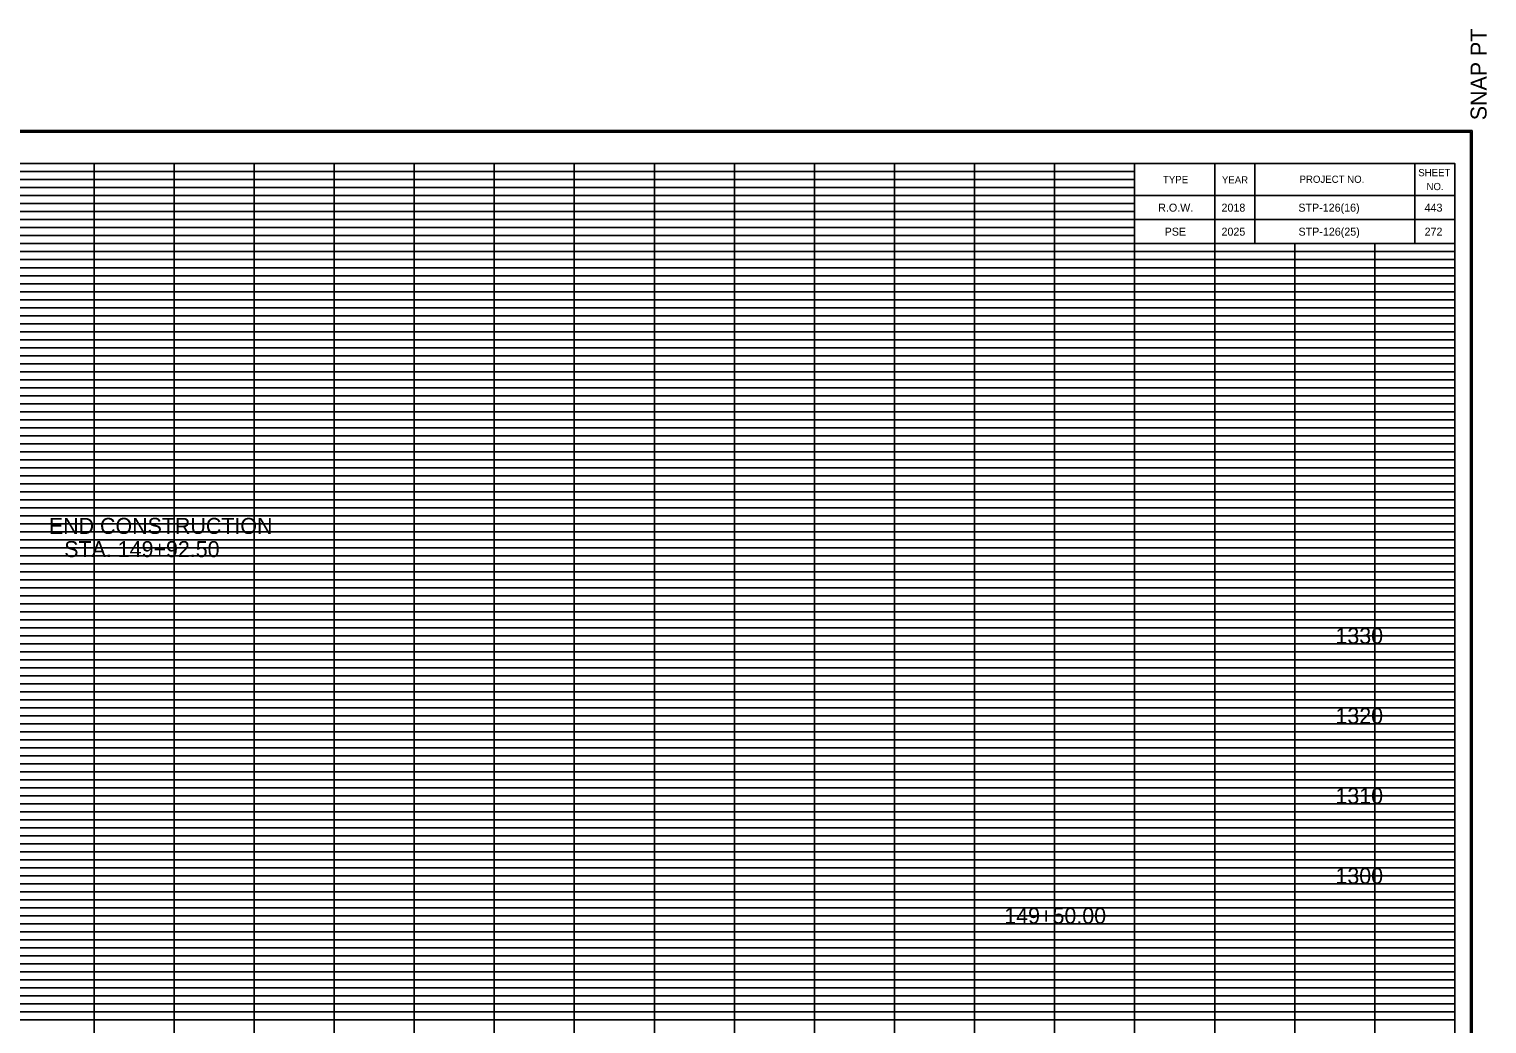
# Model space of a CAD drawing. Extents: x 980 to 1324, y 978 to 1227.
# Drawn here: x 1141.7 to 1323.8, y 1102.3 to 1226.6 of the extents above; entities that cross this region are included whole.
import ezdxf

# ---------------------------------------------------------------- set-up
doc = ezdxf.new("R2010")
doc.units = 0
for name, color, linetype in [('Default', 7, 'Continuous'), ('DESIGN - SCRATCH - User 1', 7, 'Continuous'), ('DESIGN - SHEET - Corner Text', 7, 'Continuous'), ('DESIGN - SHEET - Light Grid', 7, 'Continuous'), ('DESIGN - SHEET - Linework', 7, 'Continuous'), ('DESIGN - SHEET - Plot Shape', 7, 'Continuous'), ('DESIGN - TYPICAL - Text', 7, 'Continuous')]:
    doc.layers.add(name, color=color, linetype=linetype)

# ---------------------------------------------------------------- blocks, each defined once
blk = doc.blocks.new('XSTSHT')
at = {"layer": 'DESIGN - SCRATCH - User 1'}
for p, q in [((28.5, 20.45), (28.5, 20.45)), ((29.24, 20.45), (29.24, 20.45)), ((30.49, 20.45), (30.49, 20.45)), ((31.74, 20.45), (31.74, 20.45)), ((28.5, 20.15), (28.5, 20.15)), ((29.24, 20.15), (29.24, 20.15)), ((30.49, 20.15), (30.49, 20.15)), ((31.74, 20.15), (31.74, 20.15))]:
    blk.add_line(p, q, dxfattribs=at)
at = {"layer": 'DESIGN - SHEET - Light Grid'}
for p, q in [((8, 20.9), (16, 20.9)), ((8, 20.8), (16, 20.8)), ((16, 20.9), (24, 20.9)), ((16, 20.8), (24, 20.8)), ((24, 20.9), (28, 20.9)), ((24, 20.8), (28, 20.8)), ((8, 20.7), (16, 20.7)), ((8, 20.6), (16, 20.6)), ((16, 20.7), (24, 20.7)), ((16, 20.6), (24, 20.6)), ((24, 20.7), (28, 20.7)), ((24, 20.6), (28, 20.6)), ((8, 20.5), (16, 20.5)), ((8, 20.4), (16, 20.4)), ((16, 20.5), (24, 20.5)), ((16, 20.4), (24, 20.4)), ((24, 20.5), (28, 20.5)), ((24, 20.4), (28, 20.4)), ((8, 20.3), (16, 20.3)), ((16, 20.3), (24, 20.3)), ((24, 20.3), (28, 20.3)), ((8, 20.2), (16, 20.2)), ((8, 20.1), (16, 20.1)), ((16, 20.2), (24, 20.2)), ((16, 20.1), (24, 20.1)), ((24, 20.2), (28, 20.2)), ((24, 20.1), (28, 20.1)), ((8, 19.9), (16, 19.9)), ((16, 19.9), (24, 19.9)), ((24, 19.9), (32, 19.9)), ((8, 19.8), (16, 19.8)), ((8, 19.7), (16, 19.7)), ((16, 19.8), (24, 19.8)), ((16, 19.7), (24, 19.7)), ((24, 19.8), (32, 19.8)), ((24, 19.7), (32, 19.7)), ((8, 19.6), (16, 19.6)), ((8, 19.5), (16, 19.5)), ((16, 19.6), (24, 19.6)), ((16, 19.5), (24, 19.5)), ((24, 19.6), (32, 19.6)), ((24, 19.5), (32, 19.5)), ((8, 19.4), (16, 19.4)), ((16, 19.4), (24, 19.4)), ((24, 19.4), (32, 19.4)), ((8, 19.3), (16, 19.3)), ((8, 19.2), (16, 19.2)), ((16, 19.3), (24, 19.3)), ((16, 19.2), (24, 19.2)), ((24, 19.3), (32, 19.3)), ((24, 19.2), (32, 19.2)), ((8, 19.1), (16, 19.1)), ((16, 19.1), (24, 19.1)), ((24, 19.1), (32, 19.1)), ((8, 18.9), (16, 18.9)), ((8, 18.8), (16, 18.8)), ((16, 18.9), (24, 18.9)), ((16, 18.8), (24, 18.8)), ((24, 18.9), (32, 18.9)), ((24, 18.8), (32, 18.8)), ((8, 18.7), (16, 18.7)), ((8, 18.6), (16, 18.6)), ((16, 18.7), (24, 18.7)), ((16, 18.6), (24, 18.6)), ((24, 18.7), (32, 18.7)), ((24, 18.6), (32, 18.6)), ((8, 18.5), (16, 18.5)), ((8, 18.4), (16, 18.4)), ((16, 18.5), (24, 18.5)), ((16, 18.4), (24, 18.4)), ((24, 18.5), (32, 18.5)), ((24, 18.4), (32, 18.4)), ((8, 18.3), (16, 18.3)), ((16, 18.3), (24, 18.3)), ((24, 18.3), (32, 18.3)), ((8, 18.2), (16, 18.2)), ((8, 18.1), (16, 18.1)), ((16, 18.2), (24, 18.2)), ((16, 18.1), (24, 18.1)), ((24, 18.2), (32, 18.2)), ((24, 18.1), (32, 18.1)), ((8, 17.9), (16, 17.9)), ((16, 17.9), (24, 17.9)), ((24, 17.9), (32, 17.9)), ((8, 17.8), (16, 17.8)), ((8, 17.7), (16, 17.7)), ((16, 17.8), (24, 17.8)), ((16, 17.7), (24, 17.7)), ((24, 17.8), (32, 17.8)), ((24, 17.7), (32, 17.7)), ((8, 17.6), (16, 17.6)), ((8, 17.5), (16, 17.5)), ((16, 17.6), (24, 17.6)), ((16, 17.5), (24, 17.5)), ((24, 17.6), (32, 17.6)), ((24, 17.5), (32, 17.5)), ((8, 17.4), (16, 17.4)), ((8, 17.3), (16, 17.3)), ((16, 17.4), (24, 17.4)), ((16, 17.3), (24, 17.3)), ((24, 17.4), (32, 17.4)), ((24, 17.3), (32, 17.3)), ((8, 17.2), (16, 17.2)), ((16, 17.2), (24, 17.2)), ((24, 17.2), (32, 17.2)), ((8, 17.1), (16, 17.1)), ((16, 17.1), (24, 17.1)), ((24, 17.1), (32, 17.1)), ((8, 16.9), (16, 16.9)), ((8, 16.8), (16, 16.8)), ((16, 16.9), (24, 16.9)), ((16, 16.8), (24, 16.8)), ((24, 16.9), (32, 16.9)), ((24, 16.8), (32, 16.8)), ((8, 16.7), (16, 16.7)), ((8, 16.6), (16, 16.6)), ((16, 16.7), (24, 16.7)), ((16, 16.6), (24, 16.6)), ((24, 16.7), (32, 16.7)), ((24, 16.6), (32, 16.6)), ((8, 16.5), (16, 16.5)), ((8, 16.4), (16, 16.4)), ((16, 16.5), (24, 16.5)), ((16, 16.4), (24, 16.4)), ((24, 16.5), (32, 16.5)), ((24, 16.4), (32, 16.4)), ((8, 16.3), (16, 16.3)), ((16, 16.3), (24, 16.3)), ((24, 16.3), (32, 16.3)), ((8, 16.2), (16, 16.2)), ((8, 16.1), (16, 16.1)), ((16, 16.2), (24, 16.2)), ((16, 16.1), (24, 16.1)), ((24, 16.2), (32, 16.2)), ((24, 16.1), (32, 16.1)), ((8, 15.9), (16, 15.9)), ((16, 15.9), (24, 15.9)), ((24, 15.9), (32, 15.9)), ((8, 15.8), (16, 15.8)), ((8, 15.7), (16, 15.7)), ((16, 15.8), (24, 15.8)), ((16, 15.7), (24, 15.7)), ((24, 15.8), (32, 15.8)), ((24, 15.7), (32, 15.7)), ((8, 15.6), (16, 15.6)), ((8, 15.5), (16, 15.5)), ((16, 15.6), (24, 15.6)), ((16, 15.5), (24, 15.5)), ((24, 15.6), (32, 15.6)), ((24, 15.5), (32, 15.5)), ((8, 15.4), (16, 15.4)), ((8, 15.3), (16, 15.3)), ((16, 15.4), (24, 15.4)), ((16, 15.3), (24, 15.3)), ((24, 15.4), (32, 15.4)), ((24, 15.3), (32, 15.3)), ((8, 15.2), (16, 15.2)), ((16, 15.2), (24, 15.2)), ((24, 15.2), (32, 15.2)), ((8, 15.1), (16, 15.1)), ((16, 15.1), (24, 15.1)), ((24, 15.1), (32, 15.1)), ((8, 14.9), (16, 14.9)), ((8, 14.8), (16, 14.8)), ((16, 14.9), (24, 14.9)), ((16, 14.8), (24, 14.8)), ((24, 14.9), (32, 14.9)), ((24, 14.8), (32, 14.8)), ((8, 14.7), (16, 14.7)), ((8, 14.6), (16, 14.6)), ((16, 14.7), (24, 14.7)), ((16, 14.6), (24, 14.6)), ((24, 14.7), (32, 14.7)), ((24, 14.6), (32, 14.6)), ((8, 14.5), (16, 14.5)), ((8, 14.4), (16, 14.4)), ((16, 14.5), (24, 14.5)), ((16, 14.4), (24, 14.4)), ((24, 14.5), (32, 14.5)), ((24, 14.4), (32, 14.4)), ((8, 14.3), (16, 14.3)), ((16, 14.3), (24, 14.3)), ((24, 14.3), (32, 14.3)), ((8, 14.2), (16, 14.2)), ((8, 14.1), (16, 14.1)), ((16, 14.2), (24, 14.2)), ((16, 14.1), (24, 14.1)), ((24, 14.2), (32, 14.2)), ((24, 14.1), (32, 14.1)), ((8, 13.9), (16, 13.9)), ((16, 13.9), (24, 13.9)), ((24, 13.9), (32, 13.9)), ((8, 13.8), (16, 13.8)), ((8, 13.7), (16, 13.7)), ((16, 13.8), (24, 13.8)), ((16, 13.7), (24, 13.7)), ((24, 13.8), (32, 13.8)), ((24, 13.7), (32, 13.7)), ((8, 13.6), (16, 13.6)), ((8, 13.5), (16, 13.5)), ((16, 13.6), (24, 13.6)), ((16, 13.5), (24, 13.5)), ((24, 13.6), (32, 13.6)), ((24, 13.5), (32, 13.5)), ((8, 13.4), (16, 13.4)), ((8, 13.3), (16, 13.3)), ((16, 13.4), (24, 13.4)), ((16, 13.3), (24, 13.3)), ((24, 13.4), (32, 13.4)), ((24, 13.3), (32, 13.3)), ((8, 13.2), (16, 13.2)), ((16, 13.2), (24, 13.2)), ((24, 13.2), (32, 13.2)), ((8, 13.1), (16, 13.1)), ((16, 13.1), (24, 13.1)), ((24, 13.1), (32, 13.1)), ((8, 12.9), (16, 12.9)), ((8, 12.8), (16, 12.8)), ((16, 12.9), (24, 12.9)), ((16, 12.8), (24, 12.8)), ((24, 12.9), (32, 12.9)), ((24, 12.8), (32, 12.8)), ((8, 12.7), (16, 12.7)), ((8, 12.6), (16, 12.6)), ((16, 12.7), (24, 12.7)), ((16, 12.6), (24, 12.6)), ((24, 12.7), (32, 12.7)), ((24, 12.6), (32, 12.6)), ((8, 12.5), (16, 12.5)), ((8, 12.4), (16, 12.4)), ((16, 12.5), (24, 12.5)), ((16, 12.4), (24, 12.4)), ((24, 12.5), (32, 12.5)), ((24, 12.4), (32, 12.4)), ((8, 12.3), (16, 12.3)), ((16, 12.3), (24, 12.3)), ((24, 12.3), (32, 12.3)), ((8, 12.2), (16, 12.2)), ((8, 12.1), (16, 12.1)), ((16, 12.2), (24, 12.2)), ((16, 12.1), (24, 12.1)), ((24, 12.2), (32, 12.2)), ((24, 12.1), (32, 12.1)), ((8, 11.9), (16, 11.9)), ((16, 11.9), (24, 11.9)), ((24, 11.9), (32, 11.9)), ((8, 11.8), (16, 11.8)), ((8, 11.7), (16, 11.7)), ((16, 11.8), (24, 11.8)), ((16, 11.7), (24, 11.7)), ((24, 11.8), (32, 11.8)), ((24, 11.7), (32, 11.7)), ((8, 11.6), (16, 11.6)), ((8, 11.5), (16, 11.5)), ((16, 11.6), (24, 11.6)), ((16, 11.5), (24, 11.5)), ((24, 11.6), (32, 11.6)), ((24, 11.5), (32, 11.5)), ((8, 11.4), (16, 11.4)), ((8, 11.3), (16, 11.3)), ((16, 11.4), (24, 11.4)), ((16, 11.3), (24, 11.3)), ((24, 11.4), (32, 11.4)), ((24, 11.3), (32, 11.3)), ((8, 11.2), (16, 11.2)), ((16, 11.2), (24, 11.2)), ((24, 11.2), (32, 11.2)), ((8, 11.1), (16, 11.1)), ((16, 11.1), (24, 11.1)), ((24, 11.1), (32, 11.1)), ((8, 10.9), (16, 10.9)), ((8, 10.8), (16, 10.8)), ((16, 10.9), (24, 10.9)), ((16, 10.8), (24, 10.8)), ((24, 10.9), (32, 10.9)), ((24, 10.8), (32, 10.8)), ((8, 10.7), (16, 10.7)), ((8, 10.6), (16, 10.6)), ((16, 10.7), (24, 10.7)), ((16, 10.6), (24, 10.6)), ((24, 10.7), (32, 10.7)), ((24, 10.6), (32, 10.6)), ((8, 10.5), (16, 10.5)), ((8, 10.4), (16, 10.4)), ((16, 10.5), (24, 10.5)), ((16, 10.4), (24, 10.4)), ((24, 10.5), (32, 10.5)), ((24, 10.4), (32, 10.4)), ((8, 10.3), (16, 10.3)), ((16, 10.3), (24, 10.3)), ((24, 10.3), (32, 10.3))]:
    blk.add_line(p, q, dxfattribs=at)
at = {"layer": 'DESIGN - SHEET - Linework'}
for p, q in [((-1.823, 21.414), (32.217, 21.414)), ((32.217, 21.414), (32.217, -0.414)), ((15, 0), (15, 21)), ((16, 0), (16, 21)), ((17, 0), (17, 21)), ((18, 0), (18, 21)), ((19, 0), (19, 21)), ((20, 0), (20, 21)), ((21, 0), (21, 21)), ((22, 0), (22, 21)), ((23, 0), (23, 21)), ((24, 0), (24, 21)), ((25, 0), (25, 21)), ((26, 0), (26, 21)), ((27, 0), (27, 21)), ((0, 20), (28, 20)), ((28, 0), (28, 20)), ((29, 0), (29, 20)), ((30, 0), (30, 20)), ((31, 0), (31, 20)), ((0, 19), (32, 19)), ((0, 18), (32, 18)), ((0, 17), (32, 17)), ((0, 16), (32, 16)), ((0, 15), (32, 15)), ((0, 14), (32, 14)), ((0, 13), (32, 13)), ((0, 12), (32, 12)), ((0, 11), (32, 11))]:
    blk.add_line(p, q, dxfattribs=at)
for points in [[(0, 21), (0, 0), (32, 0), (32, 21), (0, 21)], [(28, 21), (28, 20), (32, 20), (32, 21), (31.5, 21), (31.5, 20), (29.5, 20), (29.5, 21), (29, 21), (29, 20), (32, 20), (28, 20), (28, 20.3), (32, 20.3), (32, 20.6), (28, 20.6)]]:
    blk.add_lwpolyline(points, dxfattribs=at)
at = {"layer": 'DESIGN - SHEET - Plot Shape'}
for points in [[(-1.803, 21.394), (32.197, 21.394), (32.197, -0.394), (-1.803, -0.394)], [(-0.85, 21), (32, 21), (32, -0.25), (-0.85, -0.25)]]:
    blk.add_lwpolyline(points, close=True, dxfattribs=at)
at = {"layer": 'DESIGN - SHEET - Corner Text'}
blk.add_text('  SNAP PT', height=0.2, rotation=90, dxfattribs=at).set_placement((32.397, 21.394))
for s, p in [('TYPE', (28.354, 20.756)), ('YEAR', (29.09, 20.752)), ('PROJECT NO.', (30.06, 20.76)), ('SHEET', (31.543, 20.843)), ('NO.', (31.646, 20.669))]:
    blk.add_text(s, height=0.09, dxfattribs=at).set_placement(p)

msp = doc.modelspace()

# ---------------------------------------------------------------- linework, layer by layer
at = {"layer": 'DESIGN - SHEET - Plot Shape'}
msp.add_lwpolyline([(991.3, 997.3), (1319.8, 997.3), (1319.8, 1209.8), (991.3, 1209.8)], close=True, dxfattribs=at)

# ---------------------------------------------------------------- block references
at = {"layer": 'Default', "xscale": 10, "yscale": 10}
msp.add_blockref('XSTSHT', (999.8, 999.8), dxfattribs=at)

# ---------------------------------------------------------------- texts
at = {"layer": 'DESIGN - SHEET - Corner Text'}
for s, p in [('R.O.W.', (1282.74, 1203.8)), ('R.O.W.', (1282.74, 1203.8)), ('2018', (1290.65, 1203.8)), ('STP-126(16)', (1300.25, 1203.8)), ('443', (1316.02, 1203.8)), ('PSE', (1283.55, 1200.8)), ('2025', (1290.65, 1200.8)), ('STP-126(25)', (1300.27, 1200.8)), ('272', (1316.02, 1200.8))]:
    msp.add_text(s, height=1, dxfattribs=at).set_placement(p)
at = {"layer": 'DESIGN - TYPICAL - Text'}
for s, p in [('END CONSTRUCTION', (1144.16, 1163.53)), ('STA. 149+92.50', (1146.08, 1160.63)), ('     1330     ', (1301.17, 1149.8)), ('     1320     ', (1301.17, 1139.8)), ('     1310     ', (1301.17, 1129.8)), ('     1300     ', (1301.17, 1119.8)), ('     149+50.00     ', (1259.8, 1114.82))]:
    msp.add_text(s, height=2, dxfattribs=at).set_placement(p)

doc.saveas('drawing.dxf')
